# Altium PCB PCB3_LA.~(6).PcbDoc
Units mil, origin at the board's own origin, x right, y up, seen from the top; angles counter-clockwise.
Board outline 1968 x 1968 mil, 4 copper layers (Top Layer, Internal Plane 1, Internal Plane 2, Bottom Layer), stack 18.2 mil thick; 12 components, 11 nets, 38 pads, 0 vias.
Unrouted connection lines stored in the file: 4.
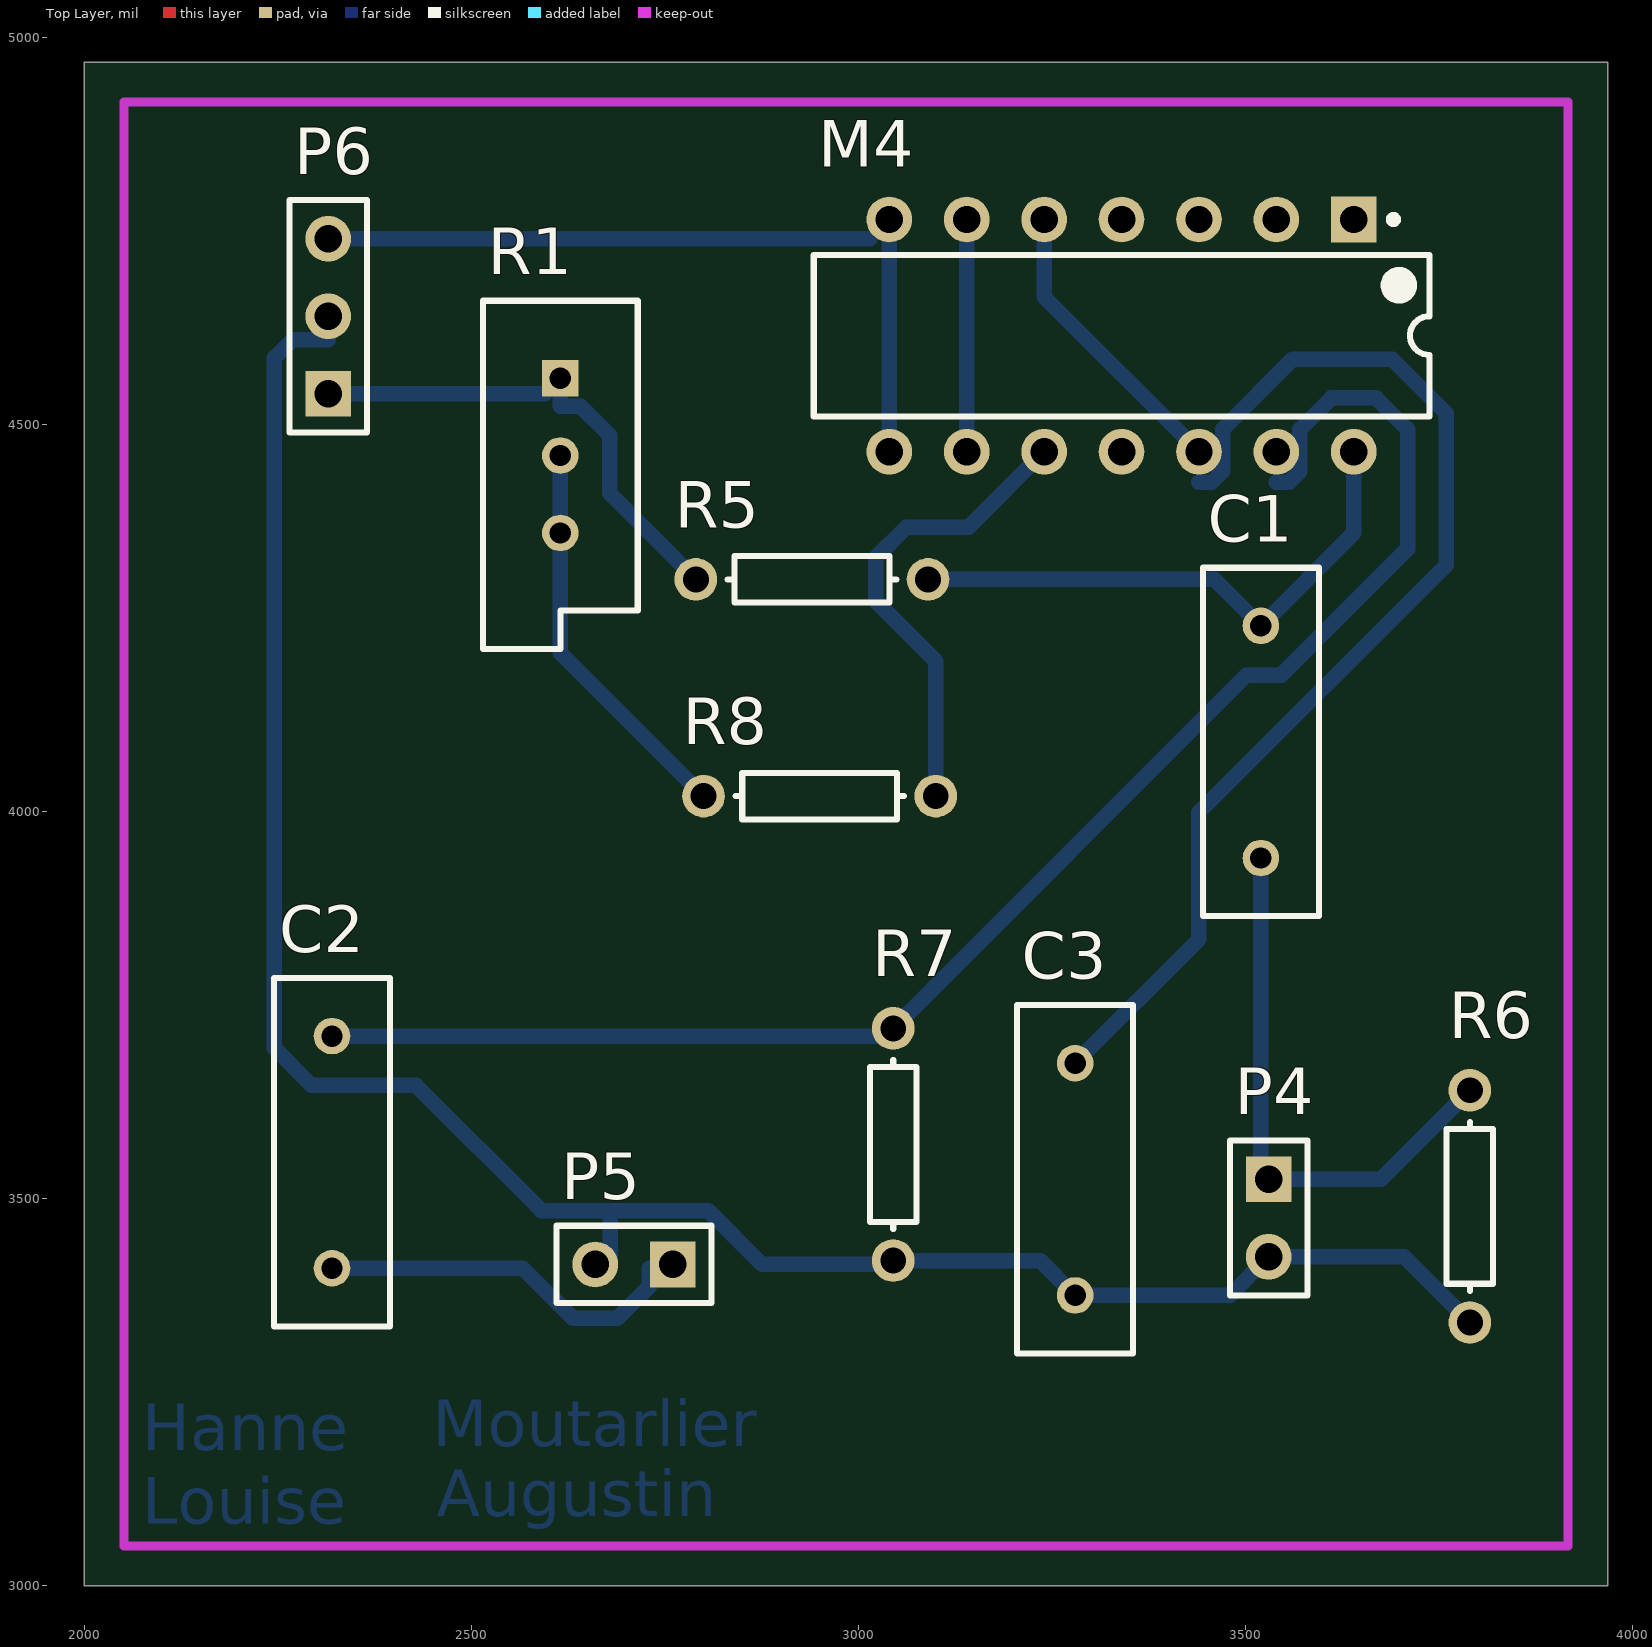
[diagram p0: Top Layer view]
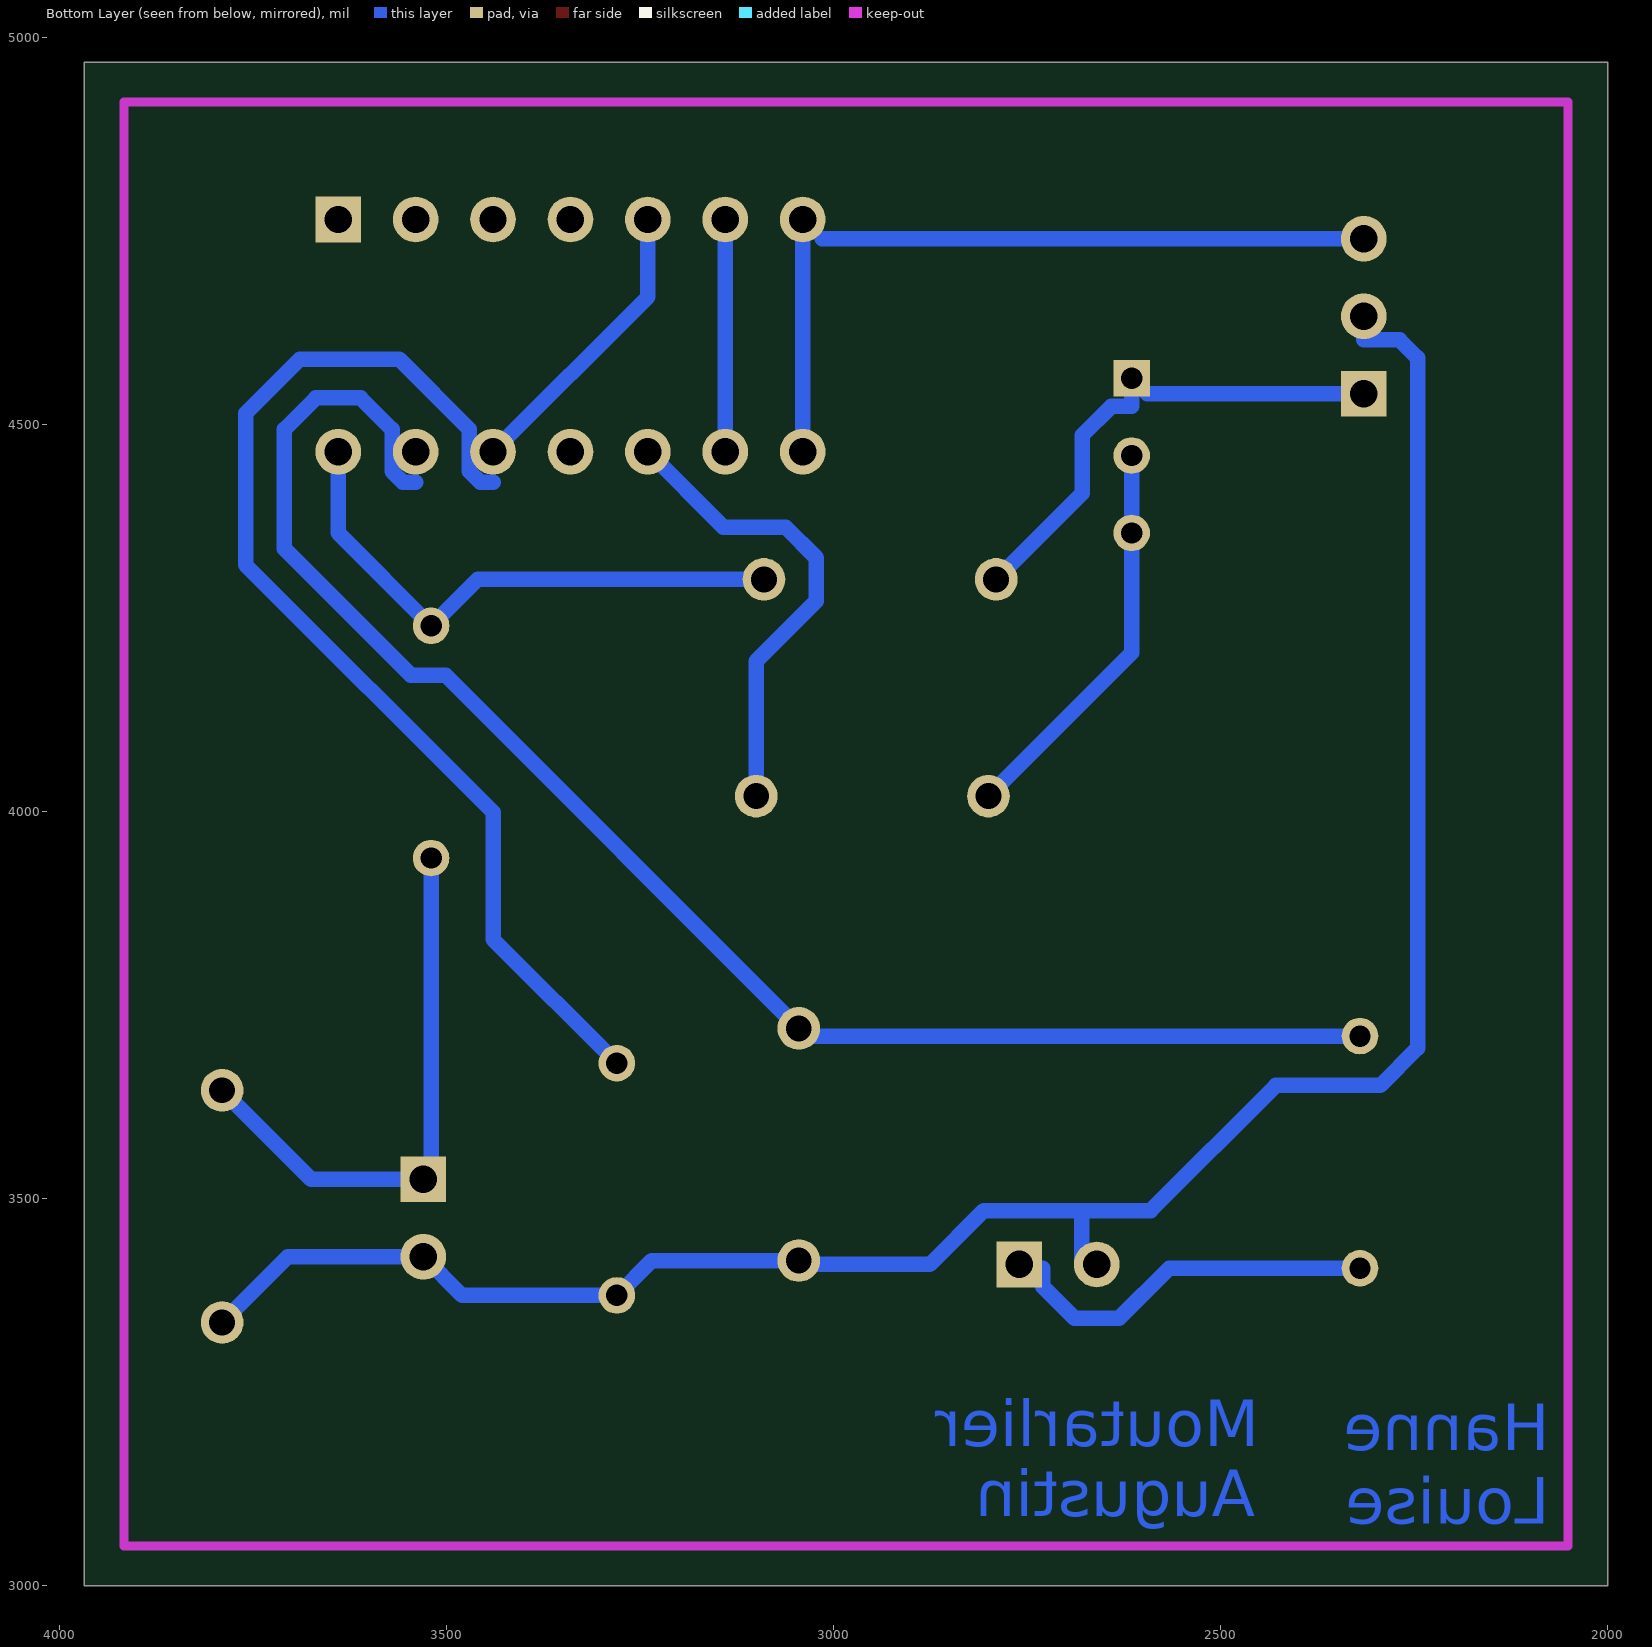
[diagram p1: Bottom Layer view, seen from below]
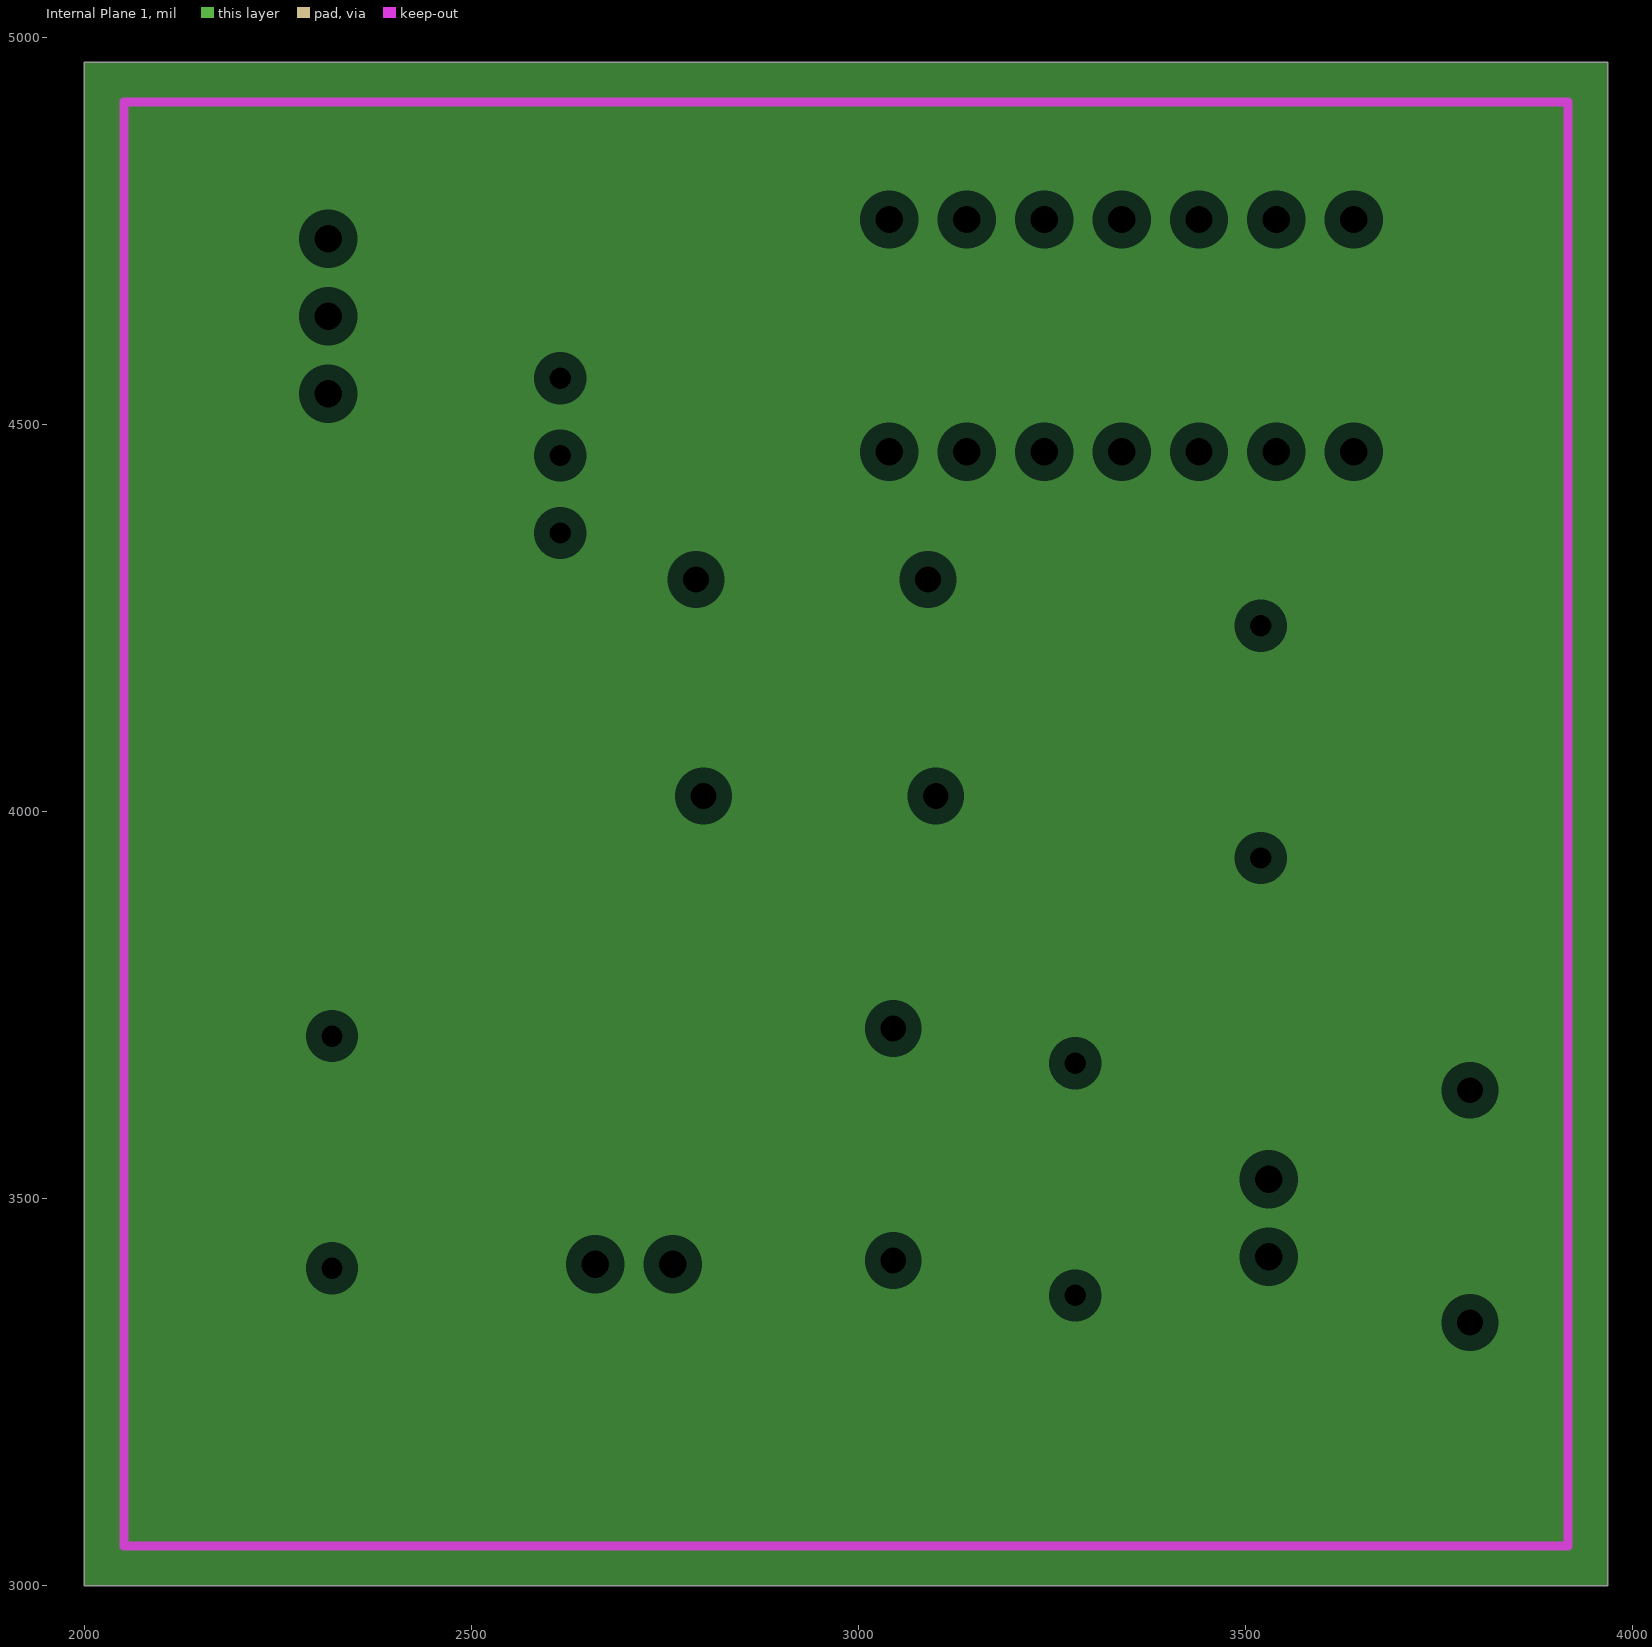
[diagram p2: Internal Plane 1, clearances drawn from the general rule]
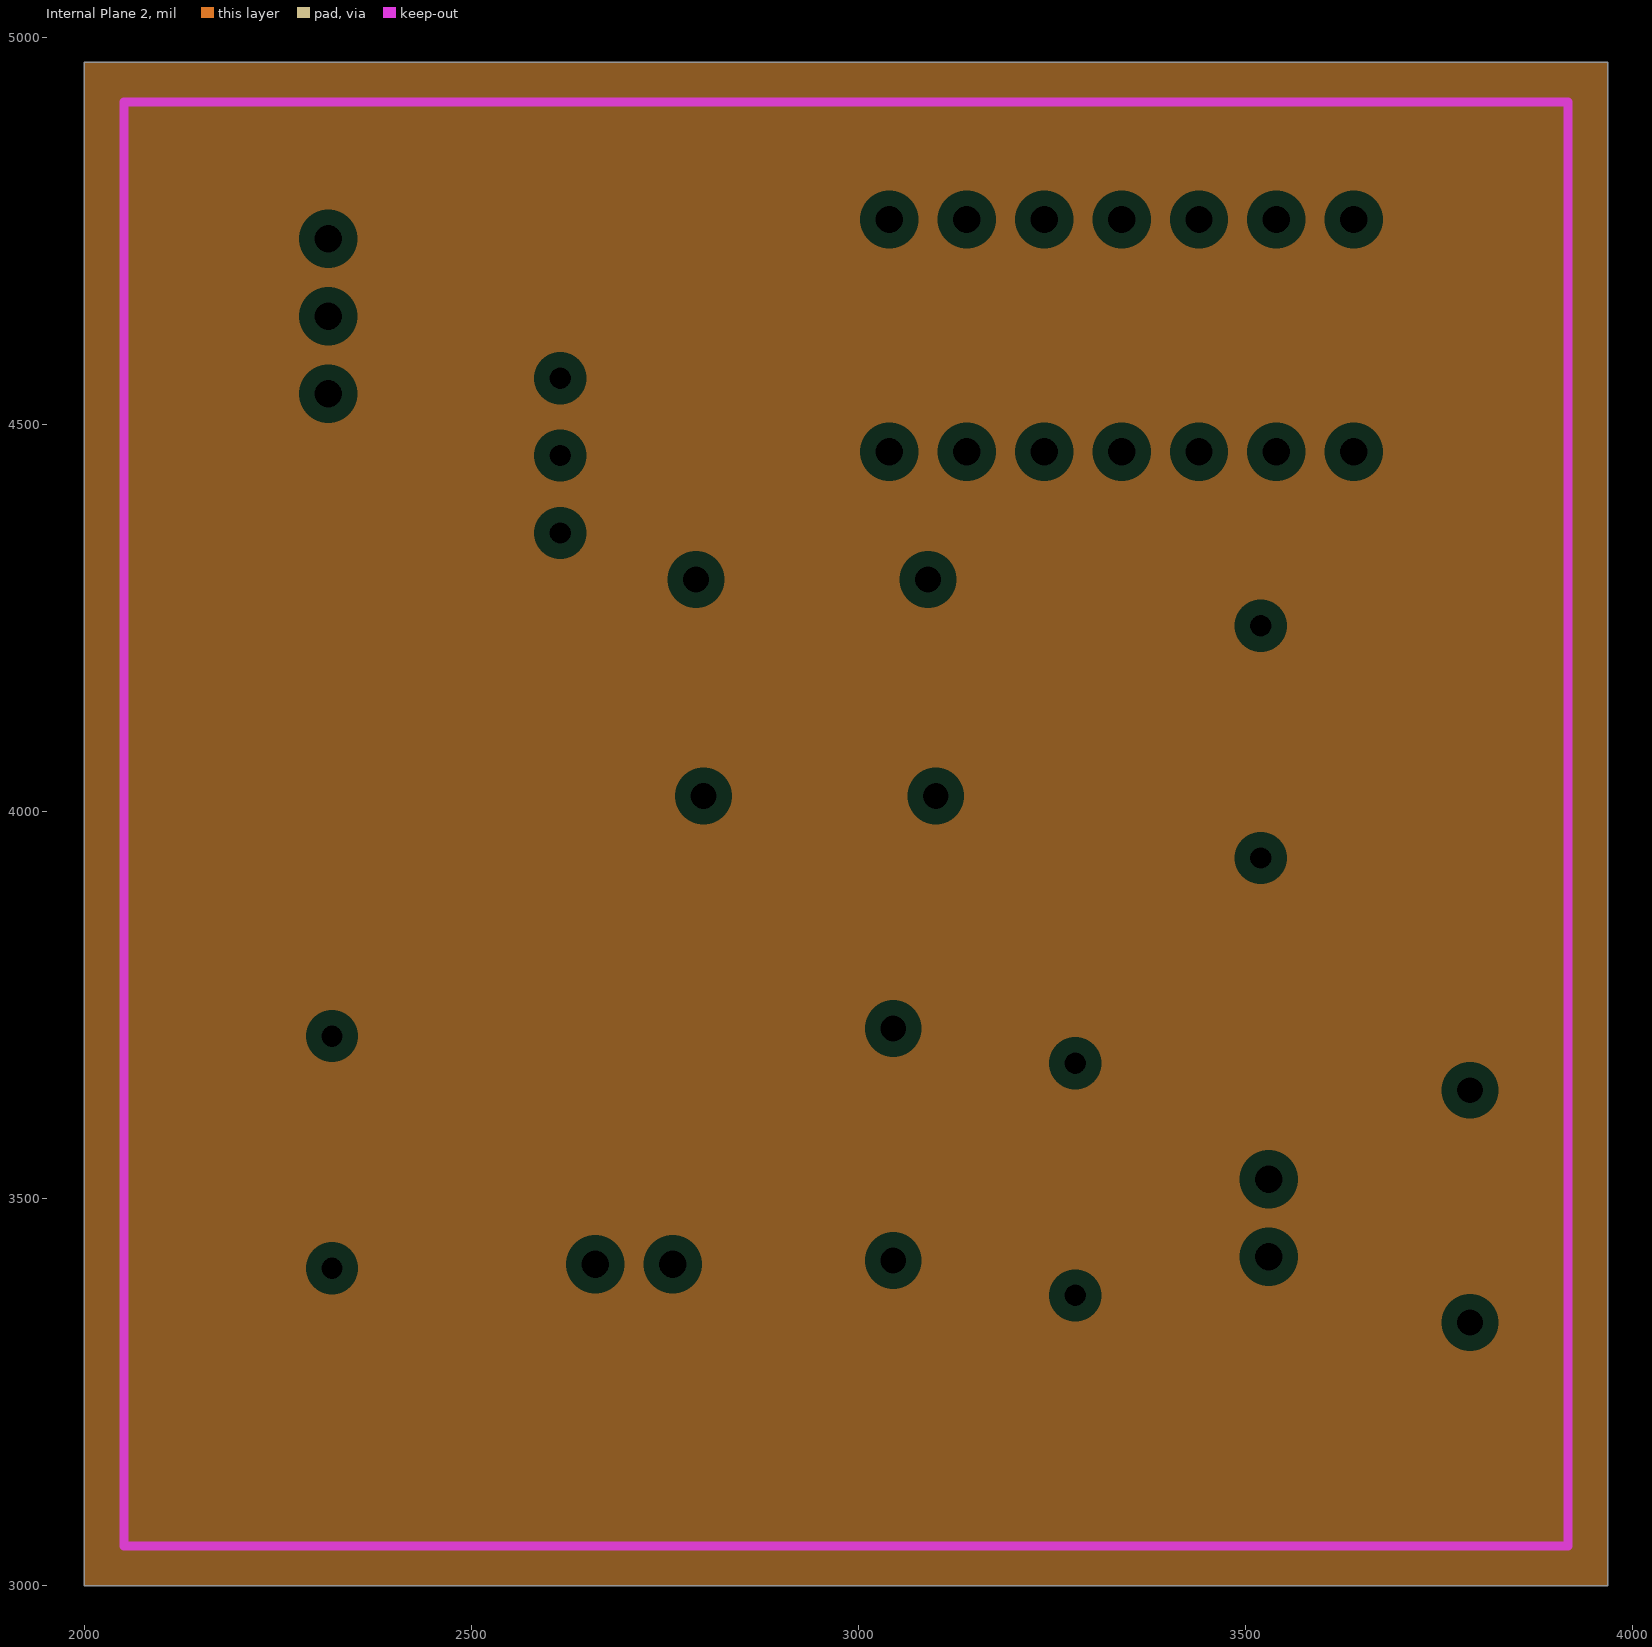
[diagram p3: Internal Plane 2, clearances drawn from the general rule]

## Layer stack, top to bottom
Top Solder: solder mask 0.4, Solder Resist, Dk 3.5
Top Layer: signal copper 1.4
Internal Plane 1: plane copper 1.4
Internal Plane 2: plane copper 1.4
Dielectric 1: dielectric 12.6, FR-4, Dk 4.8
Bottom Layer: signal copper 1.4
Bottom Solder: solder mask 0.4, Solder Resist, Dk 3.5

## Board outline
2000,3000 3968,3000 3968,4968 2000,4968

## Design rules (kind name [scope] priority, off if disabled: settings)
Clearance [All] p1: gap=30
PlaneClearance [All] p1: clearance=20
PlaneConnect [All] p1: planeconnectstyle=Relief reliefexpansion=20 reliefentries=4 reliefconductorwidth=10 reliefairgap=10
PolygonConnect [All] p1: connectstyle=Relief reliefconductorwidth=10 reliefentries=4 polygonreliefangle="90 Angle" airgapwidth=10
RoutingVias [All] p1: holewidth=32 width=62 viastyle="Through Hole" minholewidth=28 minwidth=50 maxholewidth=28 maxwidth=50
SolderMaskExpansion [All] p1: expansion=4
Width [All] p1: maxlimit=20 minlimit=20 preferedwidth=20
28 further rules are at their usual default settings.

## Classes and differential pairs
component class Project_PCB_LA: C1 C2 M4 P4 P5 P6 R1 R5 R6 R7 R8

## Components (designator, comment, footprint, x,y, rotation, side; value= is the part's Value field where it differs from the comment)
C1 "Cap" RAD-0.3 3520,4090 r90 top
C2 "Cap" RAD-0.3 2320,3560 r90 top
C3 "Cap" RAD-0.3 3280,3525 r270 top
M4 "ALD1106" DIP-14 3340,4615 r270 top
P4 "Header 2" HDR1X2 3530,3525 r270 top
P5 "Header 2" HDR1X2 2760,3415 r180 top
P6 "Header 3" HDR1X3 2315,4540 r90 top
R1 "RPot" VR5 2615,4460 r270 top
R5 "Res1" AXIAL-0.3 2940,4300 r180 top
R6 "Res1" AXIAL-0.3 3790,3490 r270 top
R7 "Res1" AXIAL-0.3 3045,3570 r270 top
R8 "Res1" AXIAL-0.3 2950,4020 r180 top

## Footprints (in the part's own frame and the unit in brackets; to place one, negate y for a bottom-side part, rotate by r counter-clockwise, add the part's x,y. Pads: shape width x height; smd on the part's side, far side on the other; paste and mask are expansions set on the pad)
AXIAL-0.3 [mm] "Axial Device, Thru-Hole; 2 Leads; 0.3 in Pin Spacing"
  round 1.4 hole 0.85: 1(-3.81,0) 2(3.81,0)
  silkscreen extent -2.77,-0.76 2.77,0.76
DIP-14 [mm] "DIP, 14-Pin, Row Spacing 7.62 mm, Pitch 2.54 mm"
  rect 1.5x1.5 hole 0.9: 1(-3.81,7.62)
  round 1.5 hole 0.9: 2(-3.81,5.08) 3(-3.81,2.54) 4(-3.81,0) 5(-3.81,-2.54) 6(-3.81,-5.08) 7(-3.81,-7.62) 8(3.81,-7.62) 9(3.81,-5.08) 10(3.81,-2.54) 11(3.81,0) 12(3.81,2.54) 13(3.81,5.08) 14(3.81,7.62)
  silkscreen extent -3.93,-10.1 2.65,10.1, body extent -3.6,-10.1 3.6,10.1, height 5.08
HDR1X2 [mm] "Connector; Header; 2 Position"
  rect 1.5x1.5 hole 0.9: 1(0,0)
  round 1.5 hole 0.9: 2(2.54,0)
  silkscreen extent -1.27,-1.27 3.81,1.27
HDR1X3 [mm] "Connector; Header; 3 Position"
  rect 1.5x1.5 hole 0.9: 1(0,0)
  round 1.5 hole 0.9: 2(2.54,0) 3(5.08,0)
  silkscreen extent -1.27,-1.27 6.35,1.27
RAD-0.3 [mm] "Radial Cap, Thru-Hole; 2 Leads; 0.3 in Pin Spacing"
  round 1.2 hole 0.7: 1(-3.81,0) 2(3.81,0)
  silkscreen extent -5.71,-1.91 5.71,1.91
VR5 [mm] "Thru-Hole; 3 Leads"
  rect 1.2x1.2 hole 0.7: 1(-2.54,0)
  round 1.2 hole 0.7: 2(0,0) 3(2.54,0)
  silkscreen extent -5.08,-2.54 6.35,2.54

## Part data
C1 C2 C3: "Capacitor"
M4: "Quad N-channel matched MOSFET array"
P4 P5: "Header, 2-Pin"
P6: "Header, 3-Pin"
R1: "Potentiometer"
R5 R6 R7 R8: "Resistor"

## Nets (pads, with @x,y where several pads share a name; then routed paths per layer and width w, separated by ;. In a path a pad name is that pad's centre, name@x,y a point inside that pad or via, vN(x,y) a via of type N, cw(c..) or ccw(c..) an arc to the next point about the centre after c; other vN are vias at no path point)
GND: C3.2 P4.2 P5.2 P6.2 R6.2 R7.2 | length 2820.2
  Bottom Layer w20: P6.2 2315,4609.53 2268.9,4609.53 2245.47,4586.1 2245.47,3694.55 2293.65,3646.38 2428.62,3646.38 2590.47,3484.53 2679.53,3484.53 ; P5.2 2679.53,3415 2679.53,3484.53 ; R7.2@3040,3415 2875.62,3415 2806.1,3484.53 2679.53,3484.53 ; R7.2 3235,3420 C3.2 3480,3375 P4.2 3705,3425 R6.2
NetC1_1: C1.1 P4.1 R6.1 | length 712.6
  Bottom Layer w20: P4.1@3520,3535 C1.1 ; P4.1 3675,3525 R6.1
NetC1_2: C1.2 M4.14 R5.1 | length 729.6
  Bottom Layer w20: R5.1 3460,4300 C1.2 3640,4360 M4.14
NetC2_1: C2.1 P5.1 | length 502.4
  Bottom Layer w20: C2.1 2566.67,3410 2631.2,3345.47 2688.8,3345.47 2729.53,3386.2 2729.53,3410 P5.1@2755,3410
NetC2_2: C2.2 M4.13 R7.1 | length 2053.7
  Bottom Layer w20: C2.2 R7.1@3035,3710 ; R7.1 3501.38,4176.38 3546.35,4176.38 3709.53,4339.55 3709.53,4493.8 3668.8,4534.53 3611.2,4534.53 3570.47,4493.8 3570.47,4439.57 3556.37,4425.47 3540,4425.47
NetC3_1: C3.1 M4.5 M4.12 | length 1867.2
  Bottom Layer w20: M4.5 3240,4665 M4.12 ; C3.1 3440,3835 3440,3999.31 3759.53,4318.84 3759.53,4514.51 3689.51,4584.53 3561.2,4584.53 3470.47,4493.8 3470.47,4439.57 3456.37,4425.47 3440,4425.47
NetM4_6: M4.6 M4.9 | length 300
  Bottom Layer w20: M4.9 M4.6
NetM4_10: M4.10 R8.1 | length 614.4
  Bottom Layer w20: R8.1 3100,4194.46 3022.44,4272.02 3022.44,4327.98 3062.02,4367.56 3142.56,4367.56 M4.10
NetR1_2: R1.2 R1.3 R8.2 | length 516.6
  Bottom Layer w20: R1.2 R1.3 2615,4205 R8.2
VDD: P6.1 R1.1 R5.2 | length 635.5
  Bottom Layer w20: P6.1 R1.1@2595,4540 ; R1.1@2610,4565 R1.1 R1.1@2615,4559.53 ; R1.1@2614.53,4559.53 R1.1@2615,4559.53 ; R5.2 2678.62,4411.38 2678.62,4486.35 2641.35,4523.62 2615,4523.62 R1.1@2615,4559.53
VSS: M4.1 M4.2 M4.3 M4.4 M4.7 M4.8 P6.3 | length 1000
  Bottom Layer w20: P6.3 3015,4740 ; M4.8 M4.7
pads on no net: M4.11

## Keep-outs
Keep-Out Layer:
  lines w11.81: 2051.18,3051.18 2051.18,4916.82 3916.82,4916.82 3916.82,3051.18 2051.18,3051.18

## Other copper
Bottom Layer:
  text "Moutarlier" at 2450,3180 h60
  text "Hanne" at 2075,3175 h60
  text "Augustin" at 2455,3090 h60
  text "Louise" at 2075,3080 h60

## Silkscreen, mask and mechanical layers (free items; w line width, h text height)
Drill Drawing:
  text ".LEGEND" at 4168,3200 h60
  text "Drill Drawing." at 4168,3100 h60

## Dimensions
2051.18,3051.18 to 2051.18,4916.82 on Mechanical 1
2051.18,3051.18 to 3916.82,3051.18 on Mechanical 1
